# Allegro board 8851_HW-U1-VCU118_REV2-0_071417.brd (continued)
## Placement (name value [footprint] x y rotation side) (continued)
C1654  1UF  [0603]  124.75 155.32 270 bottom
C1655  1UF  [0603]  126.41 155.32 270 bottom
C1656  1UF  [0603]  133.51 155.32 270 bottom
C1657  1UF  [0603]  219.16 114.04 270 top
C1658  1UF  [0603]  219.16 117.22 90 top
C1659  1UF  [0603]  227.85 96.18 270 bottom
C1660  1UF  [0603]  238.04 116.49 90 bottom
C1661  1UF  [0603]  219.16 106.8 90 top
C1662  1UF  [0603]  219.16 103.63 270 top
C1663  1UF  [0603]  219.16 93.22 270 top
C1664  1UF  [0603]  219.16 96.39 90 top
C1665  1UF  [0603]  184.69 57.85 180 top
C1666  1UF  [0603]  187.87 57.85 0 top
C1667  1UF  [0603]  173.11 52.41 90 top
C1668  1UF  [0603]  182 43.27 90 bottom
C1669  1UF  [0603]  175.34 59.26 0 top
C1670  1UF  [0603]  175.34 56.47 0 top
C1671  1UF  [0603]  152.59 138.58 270 top
C1672  1UF  [0603]  152.59 141.76 90 top
C1673  1UF  [0603]  160.21 131.23 180 top
C1674  1UF  [0603]  169.1 141.14 180 bottom
C1675  1UF  [0603]  157.04 129.87 180 top
C1676  1UF  [0603]  157.09 132.98 180 top
C1677  1UF  [0402]  210.14 113.03 270 top
C1678  1UF  [0402]  210.14 102.61 270 top
C1679  1UF  [0402]  210.14 92.2 270 top
C1680  1UF  [0402]  184.08 66.76 180 top
C1681  1UF  [0402]  143.7 138.47 270 top
C1683  DNP  [0402]  234.36 103.29 270 bottom
C1684  DNP  [0402]  236.9 103.29 270 bottom
C1685  DNP  [0402]  239.44 103.29 270 bottom
C1688  DNP  [0402]  229.91 112.69 270 bottom
C1689  DNP  [0402]  228.99 110.2 270 bottom
C1690  DNP  [0402]  227.25 104.43 90 bottom
C1691  DNP  [0402]  227.5 100.49 270 bottom
C1694  DNP  [0402]  171.84 48.73 180 top
C1695  DNP  [0402]  171.84 45.57 0 top
C1698  DNP  [0402]  163.64 130.98 270 top
C1699  DNP  [0402]  166.8 130.98 90 top
C1700  0.22UF  [0402]  210.28 115.78 270 top
C1701  0.22UF  [0402]  210.28 105.36 270 top
C1702  0.22UF  [0402]  210.28 94.95 270 top
C1703  0.22UF  [0402]  186.24 66.76 180 top
C1704  0.22UF  [0402]  143.7 140.63 270 top
C1705  1000PF  [0402]  217.64 112.39 270 top
C1706  1000PF  [0402]  217.64 101.98 270 top
C1707  1000PF  [0402]  217.64 91.56 270 top
C1708  1000PF  [0402]  182.79 59.37 180 top
C1709  1000PF  [0402]  151.96 135.87 0 top
C1712  100PF  [0402]  239.01 115.87 180 top
C1713  100PF  [0402]  227.85 109.06 270 bottom
C1714  100PF  [0402]  239.44 105.57 270 bottom
C1715  100PF  [0402]  180.6 47.71 180 bottom
C1716  100PF  [0402]  180.33 50.1 90 bottom
C1717  100PF  [0402]  164.65 139.74 270 bottom
C1718  100PF  [0402]  162.26 139.47 180 bottom
C1719  6800PF  [0402]  229.03 108.11 90 bottom
C1720  22PF  [0402]  178.3 50.1 90 bottom
C1721  22PF  [0402]  162.26 137.44 180 bottom
C1722  8200PF  [0402]  171.84 48.73 0 bottom
C1723  8200PF  [0402]  163.64 130.98 90 bottom
C1724  100PF  [0402]  171.84 43.14 180 bottom
C1725  220PF  [0402]  169.22 130.98 270 bottom
C1731  10UF  [0603]  140.59 102.28 0 top
C1732  100UF  [1206]  138.93 130.5 270 top
C1733  100UF  [1206]  113.45 105.46 180 top
C1734  100UF  [1206]  99.57 31.42 0 bottom
C1735  100UF  [1206]  93.73 31.42 180 bottom
C1736  100UF  [1206]  93.73 31.42 180 top
C1737  100UF  [1206]  120.78 108.89 0 bottom
C1738  100UF  [1206]  121.03 126.8 0 bottom
C1739  100UF  [1206]  99.57 31.42 0 top
C1740  100UF  [1206]  121.03 126.8 0 top
C1741  100UF  [1206]  105.54 31.42 180 bottom
C1742  100UF  [1206]  168.66 117.02 90 bottom
C1743  100UF  [1206]  180.1 72.13 180 top
C1744  100UF  [1206]  180.1 69.38 180 top
C1745  100UF  [1206]  169.67 86.41 90 bottom
C1746  100UF  [1206]  126.13 105.46 90 bottom
C1747  100UF  [1206]  168.66 111.18 90 bottom
C1748  100UF  [1206]  126.13 105.46 90 top
C1749  100UF  [1206]  175.64 79.93 0 bottom
C1750  100UF  [1206]  129.41 28.5 0 top
C1751  100UF  [1206]  105.54 31.42 180 top
C1752  100UF  [1206]  129.41 28.5 0 bottom
C1753  1UF  [0603]  139.63 112.79 180 top
C1754  DNP  [0402]  136.4 112.19 90 top
C1755  4.7UF  [0402]  116.46 100.51 90 top
C1756  4.7UF  [0402]  84.07 55.93 180 top
C1757  100UF  [1206]  190.26 83.62 180 top
C1758  100UF  [1206]  190.26 91.49 180 top
C1759  0.1UF  [0402]  94.25 118.43 270 bottom
C1778  DNP  [0603]  208.55 115.75 270 top
C1779  DNP  [0603]  208.55 105.33 270 top
C1780  DNP  [0603]  208.55 94.92 270 top
C1781  0.1UF  [0402]  46.25 152.93 0 top
D4  BAT54T1G  [SOD_123]  196.09 169.71 270 bottom
D5  BAT54T1G  [SOD_123]  206.25 169.71 270 bottom
D7  BAT54T1G  [SOD_123]  27.69 89.2 270 top
D8  MMSZ4680T1G  [SOD_123]  47.87 101.8 180 bottom
D9  MMSZ4683T1G  [SOD_123]  139.99 20.61 90 top
D10  BAT54T1G  [SOD_123]  203.71 169.71 270 top
D11  BAT54T1G  [SOD_123]  198.63 169.71 270 top
D12  BAT54T1G  [SOD_123]  201.17 169.71 270 bottom
D13  BAT54T1G  [SOD_123]  201.17 169.71 270 top
D14  BAT54T1G  [SOD_123]  198.63 169.71 270 bottom
D15  BAS40-04  [SOT_23]  173.45 24.93 90 bottom
D16  MMSZ4683T1G  [SOD_123]  195.11 56.39 270 top
D17  BAT54T1G  [SOD_123]  196.09 169.71 270 top
D19  MMSZ4683T1G  [SOD_123]  197.55 150.57 90 top
D32  MMSZ4683T1G  [SOD_123]  146.03 129.79 0 bottom
D33  MMSZ4680T1G  [SOD_123]  233.3 56.57 0 top
D35  BAT54T1G  [SOD_123]  206.25 169.71 270 top
D36  MMSZ4680T1G  [SOD_123]  177.23 116.99 180 top
D37  MMSZ4680T1G  [SOD_123]  175.89 73.33 270 top
D38  MMSZ4680T1G  [SOD_123]  130.27 134.16 270 top
D39  MMSZ4683T1G  [SOD_123]  136.33 103.39 90 bottom
DS1  LED-YEL-SMT  [LED_0603]  42.8 147.5 180 top
DS2  LED-GRN-RED  [HSMF_C15X]  224.69 170.3 180 top
DS3  LED-GRN-RED  [HSMF_C15X]  211.33 166.41 180 top
DS4  LED-YELLOW-SMT  [LED_0603]  206.63 162.41 270 top
DS5  LED-YELLOW-SMT  [LED_0603]  208.66 162.73 90 top
DS6  LED-GRN-SMT  [LED_0603]  219.2 170.35 270 top
DS7  LED-GRN-SMT  [LED_0603]  220.85 170.35 270 top
DS8  LED-GRN-SMT  [LED_0603]  217.55 170.35 270 top
DS9  LED-GRN-SMT  [LED_0603]  215.9 170.35 270 top
DS10  LED-GRN-SMT  [LED_0603]  213.49 170.35 270 top
DS12  LED-GRN-SMT  [LED_0603]  211.71 170.35 270 top
DS13  LED-GRN-SMT  [LED_0603]  210.06 170.35 270 top
DS14  LED-YELLOW-SMT  [LED_0603]  225.68 162.26 270 top
DS15  LED-YELLOW-SMT  [LED_0603]  224.18 166.29 270 top
DS16  LED-YELLOW-SMT  [LED_0603]  222.38 166.29 270 top
DS17  LED-YELLOW-SMT  [LED_0603]  225.91 166.29 270 top
DS18  LED-GRN-SMT  [LED_0603]  208.41 170.35 270 top
DS19  LED-YELLOW-SMT  [LED_0603]  220.73 166.28 270 top
DS20  LED-GRN-SMT  [LED_0603]  214.61 153.13 0 top
DS21  LED-YELLOW-SMT  [LED_0603]  215.27 166.28 270 top
DS24  LED-YELLOW-SMT  [LED_0603]  219.08 166.28 270 top
DS25  LED-YELLOW-SMT  [LED_0603]  230.25 167.7 270 top
DS26  LED-GRN-SMT  [LED_0603]  204.61 143.56 0 top
DS27  LED-YELLOW-SMT  [LED_0603]  223.6 162.14 270 top
DS28  LED-YELLOW-SMT  [LED_0603]  221.49 162.26 270 top
DS34  LED-BLUE-SMT  [LED_0603]  228.45 170.77 90 top
DS36  LED-YELLOW-SMT  [LED_0603]  212.85 162.72 90 top
DS42  LED-GRN-RED  [HSMF_C15X]  5.28 132.36 270 top
DS43  LED-GRN-SMT  [LED_0603]  2.34 140.21 90 top
DS44  LED-GRN-SMT  [LED_0603]  2.51 133.43 90 top
DS45  LED-RED-SMT  [LED_0603]  5.15 139.7 0 top
DS46  LED-YELLOW-SMT  [LED_0603]  219.33 162.26 270 top
DS47  LED-YELLOW-SMT  [LED_0603]  210.69 162.72 90 top
DS48  LED-YELLOW-SMT  [LED_0603]  215.01 162.72 90 top
DS49  LED-YELLOW-SMT  [LED_0603]  217.12 166.25 270 top
EMICAGE1  EMI_CAGE  [EMI_CAGE_175X225]  173.49 124.51 0 top
J1  U95-T1Y1-100A  [CON_AMP_U95_T_1Y1_100A]  42.1 59.61 90 top
J2  -  [ASP_134486_01]  152.81 164.59 0 top
J3  87832-1420  [87832_1420]  17.61 81.25 270 top
J4  ZX62D_AB_5P8  [CON_HR_ZX62D_AB_5P8]  4.12 70.79 270 top
J5  -  [HDR_1X3]  198.25 20.62 270 top
J6  FIREFLY_RECEPT  [CON_SAMTEC_UEC5_UCC8]  48.37 69.13 180 top
J7  -  [HDR_2X4]  67.56 23.93 0 top
J8  -  [HDR_1X2]  200.91 26.34 270 top
J9  -  [HDR_1X2]  64.47 23.39 270 top
J10  RJ45  [7499111221A]  36.6 170.66 180 top
J11  RED  [TP_KEY_MINI]  50.22 132.38 270 top
J12  -  [HDR_1X2]  220.74 133.27 270 top
J13  RED  [TP_KEY_MINI]  18.8 125.02 0 top
J14  -  [HDR_1X2]  124.13 144.11 0 top
J15  39-30-1060  [CON_MOL_5569_6P]  230 145.73 0 top
J16  RED  [TP_KEY_MINI]  18.8 122.35 0 top
J17  RED  [TP_KEY_MINI]  50.16 129.59 270 top
J18  RED  [TP_KEY_MINI]  11.05 144.7 270 top
J19  RED  [TP_KEY_MINI]  10.92 148.89 270 top
J20  DNP  [TP_KEY_MINI]  179.2 15.49 0 top
J21  DNP  [TP_KEY_MINI]  192.53 57.58 90 top
J22  -  [ASP_184329_01]  82.8 164.59 0 top
J23  BLACK  [TP_KEY_MINI]  222 62.28 0 top
J24  BLACK  [TP_KEY_MINI]  172.97 144.45 0 top
J25  BLACK  [TP_KEY_MINI]  224.41 16.69 0 top
J26  BLACK  [TP_KEY_MINI]  199.52 129.34 180 top
J27  BLACK  [TP_KEY_MINI]  48.77 97.97 270 top
J28  DNP  [TP_KEY_MINI]  52.1 135.94 90 top
J30  32K10K-400L5  [32K10K_400_3VIA]  29.87 99.78 270 top
J31  32K10K-400L5  [32K10K_400_3VIA]  17.93 99.78 90 top
J32  32K10K-400L5  [32K10K_400_3VIA]  58.95 111.71 0 top
J33  32K10K-400L5  [32K10K_400_3VIA]  58.95 99.78 180 top
J34  32K10K-400L5  [32K10K_400_3VIA]  83.85 132.03 270 top
J35  32K10K-400L5  [32K10K_400_3VIA]  71.91 132.03 90 top
J36  22_11_2032  [HDR_1X3_LOCK_MOLEX]  28.7 66.34 270 top
J38  BLACK  [TP_KEY_MINI]  200.28 35.61 0 top
J39  -  [HDR_BOX_2X8]  235.51 27.2 90 top
J52  HDR_2X6_F_RA  [HDR_F2X6_PMOD]  231.19 68.8 90 top
J53  -  [HDR_2X6]  236.02 91.62 270 top
J54  DNP  [TP_KEY_MINI]  201.68 141.11 0 top
J58  DNP  [TP_KEY_MINI]  197.7 143.28 270 top
J63  DNP  [TP_KEY_MINI]  131.12 117.36 180 top
J65  DNP  [TP_KEY_MINI]  64.52 95.68 0 top
J70  DNP  [TP_KEY_MINI]  38.13 111.4 180 top
J73  22_11_2032  [HDR_1X3_LOCK_MOLEX]  171.98 32.34 90 top
J78  -  [HDR_1X4]  24.97 82.7 90 top
J82  SAMTEC-TSW-106-22-F-S-RA  [SAMTEC_TSW_106_22_S_RA]  11.07 102.05 180 top
J83  -  [CON_MOL_10P_5025700893]  20.5 170.2 180 bottom
J86  DNP  [TP_KEY_MINI]  10.35 124.78 180 top
J88  DNP  [TP_KEY_MINI]  163.04 143.08 0 top
J96  U95-T1Y1-100A  [CON_AMP_U95_T_1Y1_100A]  42.1 34.03 90 top
J97  DNP  [TP_KEY_MINI]  50.39 104.54 90 top
J99  DNP  [TP_KEY_MINI]  67.04 126.31 180 top
J100  DNP  [TP_KEY_MINI]  141.61 126.31 180 top
J101  DNP  [TP_KEY_MINI]  232.62 54 270 top
J103  DNP  [TP_KEY_MINI]  201.29 30.78 180 top
J104  DNP  [TP_KEY_MINI]  64.8 138.79 90 top
J105  -  [HDR_1X6]  90.37 129.14 0 top
J106  ZX62D_AB_5P8  [CON_HR_ZX62D_AB_5P8]  4.12 83.62 270 top
J107  DNP  [TP_KEY_MINI]  189.1 77.65 180 top
J108  DNP  [TP_KEY_MINI]  173.23 74.73 0 top
J109  DNP  [TP_KEY_MINI]  132.69 138.74 270 top
J110  -  [HDR_1X2]  26.94 130.72 270 top
L1  1.0UH  [1008]  64.77 53.51 0 top
L2  1.0UH  [1008]  64.63 57.49 180 top
L3  1UH  [IND_WURTH_7040]  192.18 143.18 90 top
L4  1.0UH  [IND_IHLP2525]  50.01 89.89 90 bottom
L5  1.0UH  [IND_IHLP2525]  42.39 89.89 90 bottom
L6  FERRITE-96  [IND_LAIRD_28F0121_1SR_10]  219.93 70.03 0 top
L7  1UH  [IND_WURTH_7040]  201.26 58.85 270 top
L8  10UH  [IND_74479887310]  206.44 66.04 270 bottom
L13  FERRITE-600  [0805]  124.84 27.36 270 bottom
L22  FERRITE-96  [IND_LAIRD_28F0121_1SR_10]  173.01 133.28 180 top
L31  FERRITE-220  [0603]  85.46 29.95 90 top
L34  FERRITE-220  [0603]  6.86 73.33 180 top
L35  FERRITE-220  [0603]  7.01 68.99 180 top
L48  10UH  [IND_74479887310]  186.49 135.99 90 bottom
L60  FERRITE-600  [0805]  29.42 133.55 180 top
L61  FERRITE-600  [0805]  26.42 135.1 270 top
L62  FERRITE-120  [0603]  20.75 143.13 90 bottom
L63  1.2UH  [IND_WURTH_2828]  14.03 123.64 90 top
L65  FERRITE-96  [IND_LAIRD_28F0121_1SR_10]  38.8 129.1 90 top
L66  680NH  [IND_WURTH_7040]  49.52 112.84 0 top
L67  10UH  [IND_74479887310]  43.67 116.96 0 bottom
L70  1.0UH  [1008]  64.61 34.79 0 top
L71  1.0UH  [1008]  64.64 26.59 0 top
L72  1.0UH  [1008]  64.63 30.65 180 top
L73  3.3UH  [IND_WURTH_4838]  61.87 125.94 90 top
L74  680NH  [IND_WURTH_7040]  224.26 53.39 90 top
L75  0.68UH  [IND_WURTH_1210]  194.54 47.62 0 top
L76  FERRITE-96  [IND_LAIRD_28F0121_1SR_10]  164.39 107.03 270 top
L77  FERRITE-96  [IND_LAIRD_28F0121_1SR_10]  208.31 42.47 180 top
L79  FERRITE-96  [IND_LAIRD_28F0121_1SR_10]  190.7 16.31 90 top
L80  1UH  [IND_WURTH_7040]  153.21 124.69 180 top
L82  10UH  [IND_74479887310]  160.4 120.52 180 bottom
L83  10UH  [IND_74479887310]  221.8 46.46 90 bottom
L85  10UH  [IND_74479887310]  193.76 24.86 90 bottom
L86  1.0UH  [1008]  64.61 62.65 0 top
L87  FERRITE-600  [0805]  122.81 27.36 270 bottom
L88  220NH  [IND_WURTH_7040]  187.22 71.78 180 top
L89  220NH  [IND_WURTH_7040]  138.74 138.35 270 top
L90  FERRITE-96  [IND_LAIRD_28F0121_1SR_10]  179.38 58.34 180 top
L91  FERRITE-96  [IND_LAIRD_28F0121_1SR_10]  149.28 133.01 270 top
L92  FERRITE-835  [BEAD_LAIRD_28C0236]  231.14 130.48 180 top
L93  FERRITE-220  [0603]  6.86 86.16 180 top
L94  FERRITE-220  [0603]  7.01 81.81 180 top
L95  50NH  [IND_COIL_CLB1108_4]  201.47 104.85 0 top
L96  3.3UH  [IND_VLS252012ET_3R3M]  232.21 96.18 90 bottom
L97  3.3UH  [IND_VLS252012ET_3R3M]  175.48 54.19 0 top
L98  3.3UH  [IND_VLS252012ET_3R3M]  158.65 135.16 0 top
MH1  MH_125_250  [MH_250H125]  236.22 170.61 0 top
MH2  MH_125_250  [MH_250H125]  118.62 137.59 0 top
MH3  MH_125_250  [MH_250H125]  131.32 21.39 0 top
MH4  MH_125_250  [MH_250H125]  5.46 146.11 0 top
MH5  MH_125_250  [MH_250H125]  236.22 16.59 0 top
MH6  MH_125_250  [MH_250H125]  7.49 9.32 0 top
MH7  MH_125_250  [MH_250H125]  7.49 94.72 0 top
NOREF  -  []  60.9 43.64 0 top
NOREF#2  -  [unnamed#2]  230.12 17.81 0 top
NOREF#3  -  []  55.61 164.59 0 top
NOREF#4  -  []  58.04 172.85 0 top
NOREF#5  -  []  63.4 42.64 90 top
NOREF#6  -  []  107.57 156.34 90 top
NOREF#7  -  []  82.8 164.59 0 top
NOREF#8  -  []  58.4 41.14 0 top
NOREF#9  -  []  107.57 156.34 90 top
NOREF#10  -  [unnamed#2]  12.32 12.85 0 top
NOREF#11  -  []  58.4 45.44 0 top
NOREF#12  -  []  51.32 166.6 0 top
NOREF#13  -  []  58.4 41.14 90 top
NOREF#14  -  []  107.57 156.34 90 top
NOREF#15  -  []  59.1 41.14 0 top
NOREF#16  -  []  58.4 41.84 0 top
NOREF#17  -  []  107.57 172.85 0 top
NOREF#18  -  []  109.99 161.54 90 top
NOREF#19  -  [unnamed#2]  231.14 172.75 0 top
NOREF#20  -  []  114.31 166.6 90 top
NOREF#21  -  []  109.99 161.54 0 top
NOREF#22  -  [unnamed#2]  12.19 12.85 180 bottom
NOREF#23  -  [unnamed#2]  231.01 172.75 180 bottom
NOREF#24  -  [unnamed#2]  230 17.81 180 bottom
Q1  FDS6681Z  [SOIC_8]  215.27 145.7 270 top
Q2  RUM001L02T2CL  [SOT_723]  219.91 159.48 180 bottom
Q3  RUM001L02T2CL  [SOT_723]  2.51 130.4 0 top
Q4  BSS138  [SOT_23]  223.52 158.15 90 top
Q5  RUM001L02T2CL  [SOT_723]  216.93 156.36 0 top
Q6  RUM001L02T2CL  [SOT_723]  219.33 156.37 0 top
Q7  RUM001L02T2CL  [SOT_723]  5.58 128.43 270 top
Q8  RUM001L02T2CL  [SOT_723]  201.87 156.81 180 bottom
Q9  FDPC8011S  [PWRCLIP_33]  191.42 136.7 180 top
Q10  RUM001L02T2CL  [SOT_723]  204.03 156.3 180 bottom
Q11  RUM001L02T2CL  [SOT_723]  208.1 159.48 180 bottom
Q12  RUM001L02T2CL  [SOT_723]  210 159.48 180 bottom
Q13  RUM001L02T2CL  [SOT_723]  212.03 159.48 180 bottom
Q14  RUM001L02T2CL  [SOT_723]  213.94 159.48 180 bottom
Q15  RUM001L02T2CL  [SOT_723]  215.84 159.48 180 bottom
Q16  RUM001L02T2CL  [SOT_723]  217.88 159.48 180 bottom
Q17  RUM001L02T2CL  [SOT_723]  208.1 156.3 0 top
Q18  RUM001L02T2CL  [SOT_723]  47.91 143.2 0 top
Q19  FDPC8011S  [PWRCLIP_33]  201.52 65.33 0 top
Q20  MMBT3904T  [SOT523]  202.56 57.2 180 bottom
Q21  RUM001L02T2CL  [SOT_723]  225.99 38.76 270 bottom
Q22  RUM001L02T2CL  [SOT_723]  177.04 28.12 180 bottom
Q23  RUM001L02T2CL  [SOT_723]  225.99 36.6 270 bottom
Q24  RUM001L02T2CL  [SOT_723]  204.85 160.45 0 top
Q25  MMBT3904T  [SOT523]  190.91 145.21 0 bottom
Q26  NDS331N  [SOT_23]  204.09 160.07 90 bottom
Q27  RUM001L02T2CL  [SOT_723]  88.66 100.69 0 top
Q28  RUM001L02T2CL  [SOT_723]  174.37 27.99 90 bottom
Q34  RUM001L02T2CL  [SOT_723]  2.34 137.23 0 top
Q35  RUM001L02T2CL  [SOT_723]  5 137.61 0 top
Q36  RUM001L02T2CL  [SOT_723]  214.67 156.32 0 top
Q37  RUM001L02T2CL  [SOT_723]  206.07 156.3 0 top
Q39  FDPC8011S  [PWRCLIP_33]  42.98 112.04 90 top
Q40  MMBT3904T  [SOT523]  51.71 113.21 270 bottom
Q41  RUM001L02T2CL  [SOT_723]  210.31 156.36 0 top
Q42  FDPC8011S  [PWRCLIP_33]  159.69 124.94 270 top
Q43  FDPC8011S  [PWRCLIP_33]  226.22 46.92 180 top
Q45  FDMS8558S  [PWR_56]  192.49 38.58 90 top
Q47  FDMS8558S  [PWR_56]  183.21 39.09 90 top
Q48  MMBT3904T  [SOT523]  151.26 124.51 90 bottom
Q49  MMBT3904T  [SOT523]  225.55 55.42 0 bottom
Q51  MMBT3904T  [SOT523]  194.9 48.1 0 bottom
Q52  RUM001L02T2CL  [SOT_723]  15.37 71.68 0 bottom
Q53  RUM001L02T2CL  [SOT_723]  13.46 71.68 0 bottom
Q54  RUM001L02T2CL  [SOT_723]  21.21 66.98 180 bottom
Q55  RUM001L02T2CL  [SOT_723]  17.27 71.68 0 bottom
Q56  RUM001L02T2CL  [SOT_723]  21.21 64.82 180 bottom
Q57  RUM001L02T2CL  [SOT_723]  19.18 64.19 180 bottom
Q58  NDS331N  [SOT_23]  204.39 164.87 90 bottom
Q59  RUM001L02T2CL  [SOT_723]  41.2 142.55 180 bottom
Q60  RUM001L02T2CL  [SOT_723]  44.58 145.75 90 top
Q61  SI2300DS  [SOT_23]  172.77 37.82 180 top
R1  4.70K  [0402]  58.88 47.24 180 bottom
R2  4.70K  [0402]  58.88 48.39 180 bottom
R3  DNP  [C402-25]  117.24 54.33 180 bottom
R4  240  [0402]  151.89 50.6 0 bottom
R5  240  [0402]  131.06 31.67 270 top
R6  4.70K  [0402]  131.06 15.07 90 bottom
R7  240  [0402]  157.72 38.85 180 bottom
R8  100  [0402]  77.95 132.03 180 top
R9  100  [0402]  176.77 15.74 270 bottom
R10  15  [0402]  58.06 16.2 90 bottom
R11  DNP  [0402]  55.63 16.18 90 bottom
R12  DNP  [0402]  56.9 16.18 270 bottom
R13  4.70K  [0402]  32.89 115.49 270 bottom
R14  10  [0402]  206.34 66.34 270 top
R15  100  [0402]  154.05 68.25 270 bottom
R16  10.0K  [0402]  27.69 87.85 270 bottom
R17  1.00K  [0402]  152.91 67.25 90 bottom
R18  1.00K  [0402]  152.91 69.25 270 bottom
R19  4.70K  [0402]  109.59 170.55 180 bottom
R20  1.00K  [0402]  151.89 67.25 270 bottom
R21  4.70K  [0402]  79.88 20.5 180 top
R22  1.00K  [0402]  151.89 69.25 90 bottom
R23  1.00K  [0402]  83.57 54.39 270 top
R24  1.00K  [0402]  83.57 52.39 90 top
R25  1.00K  [0402]  84.58 54.39 90 top
R26  2.21K  [0402]  30.1 139.34 0 top
R27  2.21K  [0402]  30.1 140.61 0 top
R28  4.70K  [0402]  201.6 20.88 0 top
R29  4.70K  [0402]  30.16 131.63 0 top
R30  4.70K  [0402]  30.1 135.53 0 top
R31  4.70K  [0402]  30.1 136.8 0 top
R32  24.9  [0402]  30.1 138.07 180 top
R33  261  [0402]  42.62 147.5 180 bottom
R34  2.21K  [0402]  43.68 141.15 180 top
R35  1.00K  [0402]  32.77 130.04 90 bottom
R36  100  [0402]  205.06 15.53 0 top
R37  100  [0402]  35.42 80.79 180 bottom
R38  100  [0402]  106.81 22.23 180 bottom
R39  10.0K  [0402]  43.68 140 180 top
R40  1.00K  [0402]  61.39 72.4 180 bottom
R41  1.00K  [0402]  61.39 71.25 180 bottom
R42  1.00K  [0402]  84.58 52.39 270 top
R43  432  [0402]  59.51 63.73 180 bottom
R44  10.0K  [0402]  31.75 146.58 90 top
R45  1.00K  [0402]  203.83 29.33 90 bottom
R46  1.00K  [0402]  220.19 27.02 0 bottom
R47  1.00K  [0402]  220.19 19.4 0 bottom
R48  1.00K  [0402]  227.4 29.33 90 bottom
R49  1.00K  [0402]  220.19 30.12 0 bottom
R50  1.00K  [0402]  61.39 69.98 180 bottom
R51  1.00K  [0402]  61.39 68.71 180 bottom
R52  1.00K  [0402]  106.68 131.5 180 bottom
R53  4.70K  [0402]  101.47 136.07 0 bottom
R54  DNP  [0402]  43.68 144.2 180 bottom
R55  DNP  [0402]  43.68 143.18 180 bottom
R56  DNP  [0402]  43.68 142.16 180 bottom
R57  DNP  [0402]  43.68 136.58 180 bottom
R58  4.99K  [0402]  50 141.09 270 top
R59  4.99K  [0402]  48.72 138.85 270 bottom
R60  DNP  [0402]  41.53 132.45 90 top
R61  DNP  [0402]  36.72 132.32 90 top
R62  DNP  [0402]  43.68 144.2 0 top
R63  DNP  [0402]  43.68 143.18 0 top
R64  DNP  [0402]  43.68 142.16 0 top
R65  DNP  [0402]  43.68 137.72 0 top
R66  DNP  [0402]  40.26 132.38 270 top
R67  DNP  [0402]  35.54 132.32 270 top
R68  DNP  [0402]  43.68 136.58 180 top
R69  1.00K  [0402]  43.68 135.43 0 bottom
R70  DNP  [0402]  42.92 133.59 90 top
R71  1.00K  [0402]  41.65 133.59 270 bottom
R72  4.99K  [0402]  47.72 142.87 0 bottom
R73  1.00K  [0402]  33.78 133.63 90 bottom
R74  9.53K  [0402]  216.63 65.71 0 bottom
R75  4.99K  [0402]  61.43 140.41 180 bottom
R76  1.00K  [0402]  81.86 105.04 90 top
R77  4.70K  [0402]  116.84 24.43 180 bottom
R78  10  [0201]  194.76 60.36 90 top
R79  10  [0201]  193.76 60.36 90 top
R80  1.43K  [0402]  202.56 59.23 180 bottom
R81  261  [0402]  27.12 150.83 270 top
R82  261  [0402]  46.25 151.31 180 top
R83  15  [0402]  8.31 134.88 0 bottom
R84  1.0M  [0402]  31.8 141.61 90 top
R85  200K  [0402]  49.23 73.99 90 bottom
R86  4.70K  [0402]  96.45 29.41 180 top
R87  0.005  [RES_WSLP_1206]  191.75 149.38 0 top
R88  100  [0402]  82.42 75.21 90 top
R89  200K  [0402]  59.13 50.8 180 bottom
R90  200K  [0402]  59.13 25.23 180 bottom
R91  4.99K  [0402]  47.71 146.94 0 bottom
R92  4.99K  [0402]  47.71 148.21 0 bottom
R93  4.99K  [0402]  61.43 142.44 180 bottom
R94  4.99K  [0402]  61.43 141.42 180 bottom
R95  10  [0402]  186.6 135.69 90 top
R96  4.70K  [0402]  4.88 135.93 0 top
R97  4.70K  [0402]  2.44 135.55 0 top
R98  0  [0402]  182.81 142.34 90 bottom
R99  10  [0201]  143.88 127.38 0 bottom
R100  10  [0201]  143.88 126.74 0 bottom
R101  10  [0201]  190.2 152.25 0 top
R102  10  [0201]  190.2 151.62 0 top
R103  10  [0201]  225.01 69.14 90 top
R104  10  [0201]  224.15 69.14 90 top
R105  10.0K  [0402]  88.65 100.25 0 bottom
R106  10.0K  [0402]  202.95 160.07 270 top
R107  4.70K  [0402]  175.39 36.75 90 top
R108  240  [0402]  152.27 63.93 90 bottom
R109  10  [0201]  193.51 119.2 0 bottom
R110  10  [0201]  193.51 118.06 0 bottom
R111  10  [0201]  173.2 71.53 90 top
R112  10  [0201]  172.44 71.53 90 top
R113  10  [0201]  136.31 129.91 0 top
R114  10  [0201]  136.31 130.67 0 top
R115  4.70K  [0402]  170.53 25.18 270 bottom
R116  4.70K  [0402]  151.89 38.91 0 bottom
R117  4.70K  [0201]  202 156.43 180 top
R118  4.70K  [0201]  204.16 155.92 180 top
R119  4.70K  [0201]  208.22 159.1 180 top
R120  4.70K  [0201]  210.13 159.1 180 top
R121  4.70K  [0201]  212.16 159.1 180 top
R122  4.70K  [0201]  214.07 159.1 180 top
R123  4.70K  [0201]  215.97 159.1 180 top
R124  4.70K  [0201]  218 159.1 180 top
R125  10.0K  [0402]  146.96 117.4 180 top
R126  4.70K  [0402]  33.03 86.92 0 bottom
R127  261  [0402]  208.66 162.73 90 bottom
R128  10.0K  [0402]  173.58 64.16 180 bottom
R129  10.0K  [0402]  173.08 66.45 180 bottom
R130  10.0K  [0402]  131.23 130.03 90 bottom
R131  200K  [0402]  225.55 71.05 180 top
R132  200K  [0402]  233.17 89.46 270 bottom
R133  15  [0402]  8.31 131.43 0 bottom
R134  2.00K  [0402]  214.61 153.13 0 bottom
R135  15  [0402]  8.18 132.57 0 bottom
R136  12.7K  [0402]  216.63 68.76 0 bottom
R137  26.1K  [0402]  216.63 66.72 0 bottom
R138  8.06K  [0402]  141 18.2 0 bottom
R139  2.2  [0603]  212.18 57.07 0 top
R140  DNP  [0402]  3.04 168.47 0 bottom
R141  DNP  [0402]  216.63 67.74 180 bottom
R142  200K  [0402]  25.4 115.87 180 bottom
R143  261  [0402]  208.41 169.96 90 bottom
R144  261  [0402]  210.06 169.96 90 bottom
R145  261  [0402]  211.71 169.96 90 bottom
R146  261  [0402]  213.49 169.96 90 bottom
R147  261  [0402]  215.9 169.96 90 bottom
R148  261  [0402]  217.55 169.96 90 bottom
R149  261  [0402]  219.2 169.96 90 bottom
R150  100  [0402]  153.76 60.63 90 bottom
R151  261  [0402]  220.85 169.96 90 bottom
R152  0.005  [RES_WSLP_1206]  51.12 107.23 180 top
R153  0.001  [1206]  203.15 35.15 90 top
R154  0  [0402]  210.25 59.43 270 bottom
R155  14.7K  [0402]  176.31 135.31 180 bottom
R156  1.00K  [0402]  205.07 56.82 90 bottom
R157  2.00K  [0402]  212.54 59.31 90 bottom
R158  2.00K  [0402]  211.4 59.43 270 bottom
R159  140K  [0402]  216.63 64.69 0 bottom
R160  10.2K  [0402]  141 17.06 180 bottom
R161  0.005  [RES_WSLP_1206]  203.73 52.65 180 top
R162  10.0K  [0402]  46.96 132.59 270 top
R163  10.0K  [0402]  46.41 140.36 180 top
R164  10.0K  [0402]  204.95 158.67 180 top
R165  2.00K  [0402]  205.23 162.66 90 top
R166  34.0K  [0402]  48.11 132.59 90 top
R167  10  [0402]  212.06 81.23 0 bottom
R168  0.0005  [RES_CSS2775]  190.34 103.58 180 top
R169  499  [0402]  235.89 100.74 180 top
R170  DNP  [0805]  207.78 84 180 bottom
R171  3.01K  [0402]  235.63 103.28 270 top
R172  0.005  [RES_WSLP_1206]  136.84 99.46 180 top
R173  0.005  [RES_WSLP_1206]  140.11 15.28 0 bottom
R174  100  [0402]  153.8 56.58 90 bottom
R175  100  [0402]  151.89 83.26 0 bottom
R176  100  [0402]  96.85 100.51 90 bottom
R177  1.00K  [0402]  83.57 76.21 270 top
R178  1.00K  [0402]  83.57 74.21 90 top
R179  1.00K  [0402]  84.58 76.21 90 top
R180  1.00K  [0402]  84.58 74.21 270 top
R181  1.00K  [0402]  152.62 57.58 270 bottom
R182  1.00K  [0402]  152.62 55.58 90 bottom
R183  1.00K  [0402]  151.35 57.58 90 bottom
R184  1.00K  [0402]  151.35 55.58 270 bottom
R185  1.00K  [0402]  152.62 61.63 270 bottom
R186  1.00K  [0402]  152.62 59.63 90 bottom
R187  1.00K  [0402]  151.35 61.63 90 bottom
R188  1.00K  [0402]  151.35 59.63 270 bottom
R189  4.99K  [0402]  137 121.99 180 bottom
R190  4.99K  [0402]  137 123.26 180 bottom
R191  4.70K  [0402]  157.85 26.19 180 bottom
R192  4.70K  [0402]  177.42 37.3 0 top
R193  DNP  [0402]  179.96 38.79 270 bottom
R194  100  [0402]  105.16 23.29 90 bottom
R195  100  [0402]  115.34 122.55 180 top
R196  4.7  [0402]  217.64 81.66 90 bottom
R197  100  [0402]  126.33 111.51 90 top
R198  11.0K  [0402]  47.73 141.58 180 bottom
R199  38.3K  [0402]  176.31 136.32 180 bottom
R200  2.49K  [0402]  46.36 140.39 180 bottom
R201  11.0K  [0402]  41.96 144.73 270 bottom
R202  2.49K  [0402]  41.96 144.73 90 top
R203  11.0K  [0402]  43.65 139.84 180 bottom
R204  2.49K  [0402]  43.61 141.07 0 bottom
R205  1.00K  [0402]  39.49 134.07 0 top
R206  1.00K  [0402]  37.36 134.04 180 top
R208  4.70K  [0402]  177.42 41.5 0 top
R210  10.0K  [0402]  177.04 26.47 180 bottom
R211  10.0K  [0402]  20.98 90.43 90 bottom
R212  10.0K  [0402]  19.94 90.43 90 bottom
R213  4.70K  [0402]  177.42 38.35 0 top
R214  12.7K  [0402]  176.31 133.28 180 bottom
R215  DNP  [0402]  143.26 24.43 270 bottom
R216  0  [0402]  77.34 124.13 0 bottom
R217  4.70K  [0402]  173.74 41.83 0 top
R218  4.70K  [0402]  179.96 40.94 270 bottom
R219  10.0K  [0402]  172.72 27.99 90 bottom
R220  DNP  [0402]  169.54 41.68 0 bottom
R221  DNP  [0402]  169.54 38.53 0 bottom
R222  DNP  [0402]  169.54 40.63 180 bottom
R223  DNP  [0402]  169.54 39.58 180 bottom
R229  DNP  [0402]  177.42 40.45 180 top
R231  2.2  [0603]  180.75 144.71 180 top
R236  4.70K  [0201]  220.04 159.1 0 top
R237  39.2  [0201]  75.51 101.61 270 top
R238  39.2  [0201]  79.07 101.61 270 top
R239  39.2  [0201]  78.05 105.04 270 top
R240  39.2  [0201]  80.84 101.61 270 top
R241  39.2  [0201]  79.32 105.04 270 top
R242  39.2  [0201]  85.67 101.61 270 top
R243  39.2  [0201]  76.78 105.04 270 top
R244  39.2  [0201]  84.4 105.04 270 top
R245  39.2  [0201]  83.13 105.04 270 top
R246  39.2  [0201]  72.21 101.61 270 top
R247  39.2  [0201]  69.16 101.61 270 top
R249  39.2  [0201]  66.87 101.61 270 top
R250  39.2  [0201]  69.16 105.04 270 top
R251  39.2  [0201]  66.11 101.61 270 top
R252  39.2  [0201]  76.53 101.61 270 top
R253  39.2  [0201]  75.51 105.04 270 top
R254  39.2  [0201]  74.49 101.61 270 top
R255  39.2  [0201]  83.64 101.61 270 top
R256  39.2  [0201]  84.65 101.61 270 top
R257  39.2  [0201]  71.95 105.04 270 top
R258  402  [0201]  72.97 105.04 270 top
R259  499  [0402]  70.43 105.04 90 top
R266  100  [0402]  78.24 22.47 270 top
R273  1.00K  [0402]  223.27 155.23 180 top
R299  100  [0402]  65.41 86.79 270 top
R300  100  [0402]  65.41 84.63 270 top
R308  10.0K  [0402]  109.59 167.75 180 bottom
R316  10.0K  [0402]  214.08 148.6 180 bottom
R318  DNP  [0402]  177.42 39.4 180 top
R319  DNP  [0402]  171.83 41.2 90 top
R321  10.0K  [0402]  193.8 169.65 0 bottom
R323  10.0K  [0402]  201.55 147.26 0 bottom
R324  10.0K  [0402]  228.06 38.76 270 bottom
R327  10.0K  [0402]  225.88 33.71 0 bottom
R331  10.0K  [0402]  126.67 141.44 0 bottom
R333  4.70K  [0402]  188.04 31.85 270 bottom
R334  10.0K  [0402]  216.99 156.05 180 bottom
R345  DNP  [0402]  51.17 172.2 180 bottom
R346  DNP  [0402]  111.76 169.85 90 bottom
R352  DNP  [0402]  147.95 114.35 180 top
R354  DNP  [0402]  49.87 138.85 90 bottom
R355  DNP  [0402]  51.15 141.09 90 top
R356  DNP  [0402]  61.43 139.39 0 bottom
R362  DNP  [0402]  176.31 134.29 0 bottom
R377  240  [0402]  154.18 76.89 270 bottom
R378  240  [0402]  151.89 74.35 0 bottom
R379  240  [0402]  84.07 67.11 180 top
R380  240  [0402]  151.89 49.45 0 bottom
R383  240  [0402]  151.89 75.49 0 bottom
R384  240  [0402]  154.05 74.6 90 bottom
R385  240  [0402]  76.34 57.06 180 top
R386  240  [0402]  76.34 42.96 180 top
R388  100K  [0402]  58.55 88.82 0 top
R389  100K  [0402]  58.55 87.68 0 top
R399  0  [0402]  147.95 115.62 0 top
R418  DNP  [0402]  116.79 31.7 270 top
R421  2.00K  [0402]  225.43 150.4 90 top
R422  4.70K  [0402]  175.39 38.91 90 top
R424  1.00K  [0402]  207.14 148.51 180 top
R434  1.00K  [0402]  187.87 145.21 270 bottom
R435  1.00K  [0402]  124.13 141.57 90 top
R460  2.00K  [0402]  204.58 144.96 0 top
R463  2.00K  [0402]  180.4 142.72 270 bottom
R464  2.00K  [0402]  181.67 142.47 90 bottom
R467  2.00K  [0402]  221.49 162.26 90 bottom
R468  2.00K  [0402]  223.6 162.26 90 bottom
R472  261  [0402]  226.19 170.05 270 bottom
R473  261  [0402]  223.27 171.07 180 bottom
R478  261  [0402]  225.68 162.26 270 bottom
R479  261  [0402]  188.85 169.21 90 bottom
R480  261  [0402]  188.85 167.33 270 bottom
R481  261  [0402]  222.38 165.77 270 bottom
R482  261  [0402]  224.16 165.9 270 bottom
R483  261  [0402]  225.93 165.9 270 bottom
R484  261  [0402]  230.25 167.32 270 bottom
R486  261  [0402]  220.73 165.9 270 bottom
R487  261  [0402]  219.08 165.9 270 bottom
R488  261  [0402]  215.27 166.28 270 bottom
R492  261  [0402]  212.85 162.72 90 bottom
R498  4.99K  [0402]  15.4 63.47 180 bottom
R499  4.99K  [0402]  221.23 151.8 180 top
R500  4.99K  [0402]  225.88 34.98 0 bottom
R501  4.99K  [0402]  225.88 31.17 0 bottom
R502  4.99K  [0402]  225.88 32.44 0 bottom
R515  140K  [0402]  176.31 137.34 180 bottom
R547  DNP  [0402]  133.86 31.67 90 bottom
R548  1.00K  [0402]  132.72 31.67 270 bottom
R553  200  [0402]  27.69 85.24 0 top
R554  200  [0402]  27.69 82.7 0 top
R556  100  [0201]  70.92 45.94 90 top
R557  100  [0201]  71.56 45.94 270 top
R558  100  [0201]  70.92 31.84 90 top
R559  100  [0201]  71.56 31.84 270 top
R560  1.00K  [0402]  131.57 31.67 270 bottom
R563  24.9  [0402]  164.1 15.22 0 top
R564  39.2  [0201]  71.19 101.61 270 top
R565  36  [0402]  83.27 95.03 0 top
R566  36  [0402]  83.26 93.76 0 top
R567  39.2  [0201]  66.87 105.04 270 top
R568  39.2  [0201]  85.67 105.04 270 top
R569  39.2  [0201]  65.86 105.04 270 top
R573  15  [0402]  9.32 156.36 0 bottom
R574  15  [0402]  9.32 158.26 0 bottom
R575  15  [0402]  5.26 171.09 0 bottom
R580  DNP  [0402]  140.79 115.64 0 bottom
R581  DNP  [0402]  137.01 115.64 0 bottom
R582  DNP  [0402]  140.78 114.36 180 top
R594  1.00K  [0402]  84.58 70.77 90 top
R595  1.00K  [0402]  84.58 68.77 270 top
R596  1.00K  [0402]  83.57 70.77 270 top
R597  1.00K  [0402]  83.57 68.77 90 top
R598  220  [0402]  228.45 170.82 90 bottom
R600  4.99K  [0402]  142.84 115.64 0 bottom
R601  4.99K  [0402]  137.01 114.36 0 top
R602  4.99K  [0402]  140.78 114.37 0 bottom
R603  4.99K  [0402]  50.89 142.87 0 top
R604  4.99K  [0402]  50.89 144.27 0 top
R607  4.99K  [0402]  47.72 144.52 0 bottom
R608  4.99K  [0402]  47.72 145.66 0 bottom
R611  4.99K  [0402]  61.41 149.08 180 bottom
R612  4.99K  [0402]  61.43 147.95 180 bottom
R613  4.99K  [0402]  61.43 146.82 180 bottom
R614  4.99K  [0402]  61.43 145.71 180 bottom
R617  4.99K  [0402]  61.43 144.58 180 bottom
R618  4.99K  [0402]  61.43 143.46 180 bottom
R621  4.99K  [0402]  140.54 116.78 0 bottom
R622  4.99K  [0402]  140.54 117.93 0 bottom
R623  4.99K  [0402]  140.54 119.07 0 bottom
R624  4.99K  [0402]  140.54 121.36 0 bottom
R625  4.99K  [0402]  140.54 120.21 0 bottom
R626  4.99K  [0402]  140.54 123.64 0 bottom
R627  4.99K  [0402]  140.54 122.5 0 bottom
R628  4.99K  [0402]  142.39 124.06 270 bottom
R629  4.99K  [0402]  137 124.53 180 bottom
R630  4.99K  [0402]  137 125.8 180 bottom
R637  1.50K  [0402]  226.19 153.07 270 top
R638  3.32K  [0402]  226.44 156.88 270 top
R639  10.0K  [0402]  224.92 153.07 270 bottom
R640  1.00K  [0402]  224.92 153.07 270 top
R682  4.99K  [0402]  58.44 138.77 90 bottom
R683  4.99K  [0402]  59.71 138.77 90 bottom
R687  100  [0402]  109.6 26.09 90 top
R692  100  [0402]  82.42 53.39 90 top
R700  240  [0402]  102.54 100.51 90 top
R704  240  [0402]  76.34 71.15 180 top
R705  240  [0402]  76.34 99.35 180 top
R706  100  [0201]  70.92 60.03 90 top
R707  100  [0201]  71.56 60.03 270 top
R708  100  [0201]  70.49 89.5 90 top
R709  100  [0201]  71.13 89.5 270 top
R712  1.43K  [0402]  190.37 143.05 0 bottom
R724  4.70K  [0402]  28.53 133.55 180 bottom
R726  4.70K  [0402]  5.84 128.8 180 bottom
R727  4.70K  [0402]  14.88 108.24 180 top
R728  4.70K  [0402]  14.88 109.51 180 top
R729  4.70K  [0402]  14.88 110.78 180 top
R730  4.70K  [0402]  14.88 112.05 180 top
R748  330  [0402]  2.61 128.56 180 top
R756  1.78K  [0402]  186.9 31.85 90 bottom
R772  20K  [0402]  24.31 132.13 0 bottom
R773  20K  [0402]  24.31 134.67 0 bottom
R774  20K  [0402]  24.31 133.4 0 bottom
R775  20K  [0402]  22.7 136.5 90 bottom
R776  20K  [0402]  24.31 135.94 180 bottom
R784  261  [0402]  5.94 134.26 90 bottom
R785  261  [0402]  5.64 140.59 90 bottom
R786  261  [0402]  5.21 141.15 0 top
R787  261  [0402]  5.87 131.59 270 bottom
R792  4.70K  [0402]  162.18 24.69 90 top
R793  4.70K  [0402]  163.39 24.68 90 top
R796  DNP  [C402-25]  112.24 72.33 180 bottom
R798  DNP  [C402-25]  123.75 70.84 90 bottom
R799  24.9  [0402]  160.7 19.27 270 top
R801  DNP  [0402]  162.18 15.59 270 top
R802  DNP  [0402]  168 15.22 90 top
R803  0  [0402]  160.96 15.59 90 top
R804  0  [0402]  168.01 17.4 90 top
R805  4.02K  [0402]  10.71 118.25 180 bottom
R808  5.9K  [0402]  27.43 112.57 180 bottom
R809  4.32K  [0402]  31.01 106.55 270 bottom
R810  15  [0402]  8.18 137.16 0 bottom
R811  15  [0402]  8.18 136.02 0 bottom
R812  15  [0402]  8.31 133.71 0 bottom
R813  3.65K  [0402]  10.73 119.39 180 bottom
R814  2.67K  [0402]  10.71 117.11 0 bottom
R815  3.32K  [0402]  27.41 108.82 180 bottom
R816  10.0K  [0402]  27.41 111.36 0 bottom
R817  10.0K  [0402]  30.1 114.99 0 bottom
R818  10.0K  [0402]  32.28 106.55 90 bottom
R819  10.0K  [0402]  27.41 107.55 0 bottom
R820  10.0K  [0402]  228.06 36.6 270 bottom
R821  10.0K  [0402]  35.28 106.35 180 bottom
R823  10.0K  [0402]  17 119.2 180 top
R824  10.0K  [0402]  42.29 105.64 270 bottom
R826  4.70K  [0402]  23.85 130.32 90 bottom
R827  20K  [0402]  31.75 115.49 90 bottom
R828  20K  [0402]  14.16 120.21 90 bottom
R830  2.00K  [0402]  219.33 162.34 90 bottom
R832  26.1K  [0402]  35.28 107.49 0 bottom
R837  68.1  [0402]  220.19 14.85 180 bottom
R838  68.1  [0402]  220.19 22.5 180 bottom
R839  68.1  [0402]  221.71 34.64 180 bottom
R840  68.1  [0402]  208.35 29.21 270 bottom
R841  68.1  [0402]  222.88 29.33 270 bottom
R854  4.70K  [0402]  13.29 114.25 90 top
R855  4.70K  [0402]  13.29 111.71 90 top
R856  4.70K  [0402]  13.29 109.17 90 top
R857  4.70K  [0402]  13.29 106.63 90 top
R858  4.70K  [0402]  10.04 71.56 90 bottom
R859  10.0K  [0402]  11.44 71.53 90 bottom
R860  DNP  [0402]  10.71 69.65 180 bottom
R861  10.0K  [0402]  55.02 149.61 270 bottom
R888  4.70K  [0402]  179.58 168.03 180 bottom
R890  10.0K  [0402]  179.58 165.24 180 bottom
R891  DNP  [0402]  120.69 170.46 180 bottom
R892  DNP  [0402]  181.29 169.53 180 bottom
R893  240  [0402]  76.34 85.25 180 top
R894  100  [0201]  70.92 74.13 90 top
R895  100  [0201]  71.56 74.13 270 top
R896  1.00K  [0402]  165 100.22 270 bottom
R897  36  [0402]  169.9 90.34 0 bottom
R898  36  [0402]  169.9 91.61 0 bottom
R899  499  [0402]  153.57 100.22 270 bottom
R900  100  [0402]  146.56 105.33 270 top
R901  100  [0402]  144.53 104.06 180 top
R902  39.2  [0201]  161.57 104.03 90 bottom
R903  39.2  [0201]  166.27 100.22 90 bottom
R904  39.2  [0201]  164.11 104.03 90 bottom
R905  39.2  [0201]  163.73 100.22 90 bottom
R906  39.2  [0201]  158.65 100.22 90 bottom
R907  39.2  [0201]  168.81 100.22 90 bottom
R908  39.2  [0201]  157.38 100.22 90 bottom
R909  39.2  [0201]  168.81 104.03 90 bottom
R910  39.2  [0201]  159.92 100.22 90 bottom
R911  39.2  [0201]  159.03 104.03 90 bottom
R912  39.2  [0201]  154.08 104.03 90 bottom
R913  39.2  [0201]  157.76 104.03 90 bottom
R914  39.2  [0201]  151.03 100.22 90 bottom
R915  39.2  [0201]  149.76 100.22 90 bottom
R916  39.2  [0201]  160.3 104.03 90 bottom
R917  39.2  [0201]  165.38 104.03 90 bottom
R918  39.2  [0201]  162.46 100.22 90 bottom
R919  39.2  [0201]  166.27 104.03 90 bottom
R920  39.2  [0201]  170.08 104.03 90 bottom
R921  39.2  [0201]  152.3 100.22 90 bottom
R922  402  [0201]  156.11 100.22 90 bottom
R923  39.2  [0201]  152.94 104.03 90 bottom
R924  39.2  [0201]  155.22 104.03 90 bottom
R925  39.2  [0201]  170.08 100.22 90 bottom
R926  39.2  [0201]  151.79 103.9 90 top
R928  100K  [0402]  145.16 98.98 0 bottom
R929  100K  [0402]  145.29 100.38 0 bottom
R930  240  [0402]  157.72 53.08 180 bottom
R931  240  [0402]  157.72 67.17 180 bottom
R932  240  [0402]  157.72 81.4 180 bottom
R933  240  [0402]  157.72 95.49 180 bottom
R934  4.70K  [0402]  109.6 159.62 180 bottom
R935  100  [0201]  165.09 43.04 90 bottom
R936  100  [0201]  164.45 43.04 270 bottom
R937  100  [0201]  165.09 57.14 90 bottom
R938  100  [0201]  164.45 57.14 270 bottom
R939  100  [0201]  165.09 71.24 90 bottom
R940  100  [0201]  164.45 71.24 270 bottom
R941  100  [0201]  165.09 85.33 90 bottom
R942  100  [0201]  164.45 85.33 270 bottom
R943  100  [0201]  165.09 28.82 90 bottom
R944  100  [0201]  164.45 28.82 270 bottom
R945  261  [0402]  210.69 162.72 90 bottom
R951  36  [0402]  94.5 116.38 90 bottom
R952  39.2  [0201]  102.24 121.52 180 top
R953  39.2  [0201]  95.4 125.96 270 top
R954  39.2  [0201]  92.23 108.36 90 top
R955  39.2  [0201]  84.25 120.17 0 top
R956  39.2  [0201]  102.24 116.57 180 top
R957  39.2  [0201]  102.24 120.76 180 top
R958  39.2  [0201]  84.25 112.17 0 top
R959  39.2  [0201]  84.25 114.17 0 top
R960  39.2  [0201]  84.25 111.17 0 top
R961  39.2  [0201]  102.24 114.66 180 bottom
R962  39.2  [0201]  102.24 116.57 180 bottom
R963  39.2  [0201]  84.25 115.17 0 top
R964  39.2  [0201]  84.25 119.17 0 top
R965  39.2  [0201]  89.23 108.36 90 top
R966  39.2  [0201]  84.25 117.17 0 top
R967  39.2  [0201]  94.49 125.91 270 top
R968  39.2  [0201]  102.24 115.55 180 top
R969  39.2  [0201]  102.24 120.76 180 bottom
R970  39.2  [0201]  84.25 113.17 0 top
R971  39.2  [0201]  84.25 118.17 0 top
R972  39.2  [0201]  102.24 117.33 180 top
R973  39.2  [0201]  102.24 117.33 180 bottom
R974  39.2  [0201]  102.24 114.66 180 top
R975  39.2  [0201]  91.23 108.36 90 top
R976  39.2  [0201]  96.11 108.34 90 top
R977  39.2  [0201]  90.23 108.36 90 top
R978  39.2  [0201]  102.24 115.55 180 bottom
R988  100  [0402]  93.73 124.13 0 bottom
R989  100  [0402]  100.36 108.01 270 bottom
R990  39.2  [0201]  86.23 118.54 270 bottom
R991  100  [0402]  56.24 135.9 270 bottom
R992  100  [0402]  54.63 135.36 180 bottom
R1001  240  [0402]  84.96 91.62 270 bottom
R1002  240  [0402]  84.96 78.54 90 bottom
R1007  249  [0402]  78.87 124.89 180 top
R1008  100K  [0402]  57.29 131.15 0 top
R1009  100K  [0402]  58.83 131.43 270 top
R1013  261  [0402]  215.01 162.72 90 bottom
R1015  2.40K  [0402]  143.36 19.07 270 top
R1016  4.70K  [0402]  142.88 26.21 0 top
R1017  DNP  [0402]  157.61 24.18 270 top
R1018  4.70K  [0402]  157.35 17.8 270 top
R1019  4.70K  [0402]  143.51 18.21 270 bottom
R1020  4.70K  [0402]  50.4 124.08 180 top
R1021  10  [0402]  43.36 116.86 0 top
R1022  0  [0402]  50.27 120.77 0 bottom
R1023  DNP  [C402-25]  125.24 57.33 0 bottom
R1024  DNP  [C402-25]  136.24 52.33 0 bottom
R1028  12.7K  [0402]  40.95 126.67 90 bottom
R1029  2.2  [0603]  52.63 122.7 90 top
R1052  1.78K  [0402]  50.4 124.08 0 bottom
R1070  DNP  [0402]  41.96 126.67 270 bottom
R1071  240  [0402]  84.07 58.34 180 top
R1072  240  [0402]  83.54 43.3 180 top
R1073  240  [0402]  84.07 59.49 180 top
R1074  1.00K  [0402]  50.85 115.59 180 bottom
R1075  2.00K  [0402]  50.4 123.06 180 bottom
R1076  2.00K  [0402]  50.27 121.92 0 bottom
R1077  140K  [0402]  45.01 126.77 90 bottom
R1078  26.1K  [0402]  44 126.67 90 bottom
R1079  953  [0402]  49.28 112.19 270 bottom
R1083  1.21K  [0402]  120.77 31.77 90 top
R1084  1.21K  [0402]  122.04 31.77 90 top
R1085  1.21K  [0402]  123.43 31.77 90 top
R1087  1.21K  [0402]  124.58 31.77 90 top
R1088  100  [0402]  136.02 31.55 90 bottom
R1090  4.02K  [0402]  57.46 118.3 270 bottom
R1092  4.70K  [0402]  62.84 63.86 270 bottom
R1094  4.70K  [0402]  58.88 21.67 180 bottom
R1095  4.70K  [0402]  58.88 22.81 180 bottom
R1096  12.7K  [0402]  59.13 118.67 180 top
R1097  3.65K  [0402]  57.61 120.95 90 top
R1100  20K  [0402]  60.48 120.86 270 bottom
R1101  4.70K  [0402]  21.69 156.49 180 bottom
R1103  DNP  [0402]  7.92 160.93 270 bottom
R1104  DNP  [0402]  9.32 160.93 270 bottom
R1105  39.2  [0201]  70.23 101.64 270 top
R1106  39.2  [0201]  149.3 103.85 90 top
R1107  953  [0402]  225.55 53.52 0 bottom
R1108  26.1K  [0402]  211.65 46.74 180 bottom
R1109  68.1K  [0402]  183.6 23.97 180 bottom
R1111  10  [0402]  160.71 119.99 180 top
R1112  0  [0402]  153.8 116.71 180 bottom
R1113  10  [0402]  221.9 46.15 90 top
R1114  0  [0402]  217.99 53.06 90 bottom
R1116  10  [0402]  195.79 20.54 90 top
R1124  4.70K  [0402]  22.91 139.09 90 bottom
R1125  38.3K  [0402]  160.07 110.34 270 bottom
R1126  21.5K  [0402]  211.62 45.77 180 bottom
R1127  1.43K  [0402]  153.54 124 90 bottom
R1130  12.7K  [0402]  183.6 22.7 180 bottom
R1131  12.7K  [0402]  163.12 110.34 270 bottom
R1132  12.7K  [0402]  161.09 110.32 270 bottom
R1133  12.7K  [0402]  211.62 43.74 180 bottom
R1135  6.19K  [0402]  192.53 51.49 0 bottom
R1136  2.2  [0603]  151.43 114.78 270 top
R1137  2.2  [0603]  215.55 55.42 180 top
R1139  2.2  [0603]  191.34 44.17 0 bottom
R1140  100  [0402]  175.94 20.05 0 top
R1141  100  [0402]  84.36 116.26 0 bottom
R1142  100  [0402]  67.21 113.85 0 bottom
R1143  DNP  [0402]  162.1 110.34 90 bottom
R1144  DNP  [0402]  211.62 44.76 0 bottom
R1145  249  [0402]  84.99 121.6 180 top
R1147  0  [0402]  191.85 31.85 90 bottom
R1148  0  [0402]  102.64 119.57 0 bottom
R1154  1.00K  [0402]  151.18 121.89 0 bottom
R1155  1.00K  [0402]  223.17 55.68 270 bottom
R1157  1.00K  [0402]  202.39 43.4 180 top
R1158  2.00K  [0402]  153.67 114.42 0 bottom
R1159  2.00K  [0402]  153.8 115.57 180 bottom
R1160  2.00K  [0402]  215.7 53.19 270 bottom
R1161  2.00K  [0402]  216.85 53.06 90 bottom
R1164  2.00K  [0402]  189.31 31.85 270 bottom
R1165  2.00K  [0402]  190.58 31.85 90 bottom
R1166  140K  [0402]  159.05 110.34 270 bottom
R1167  140K  [0402]  211.62 47.8 180 bottom
R1169  140K  [0402]  183.6 26.51 180 bottom
R1170  51.1K  [0402]  183.6 25.24 180 bottom
R1171  0.005  [RES_WSLP_1206]  146.32 127 90 top
R1172  0.005  [RES_WSLP_1206]  227.06 58.95 0 top
R1174  59.0K  [0402]  42.98 126.67 90 bottom
R1177  100  [0402]  82.42 69.77 90 top
R1183  261  [0402]  217.17 166.28 270 bottom
R1190  432  [0402]  58.45 36.17 0 bottom
R1192  10.0K  [0402]  62.56 120.75 180 bottom
R1193  10.0K  [0402]  98.1 126.22 90 bottom
R1194  10.0K  [0402]  95.56 126.35 90 bottom
R1195  10.0K  [0402]  100.64 126.22 90 bottom
R1196  20K  [0402]  21.51 134.11 180 bottom
R1197  20K  [0402]  24.94 143.87 0 top
R1198  100  [0402]  78.24 24.88 270 top
R1199  DNP  [0402]  183.27 43.01 90 bottom
R1200  DNP  [0402]  169.35 142.41 180 bottom
R1201  200  [0402]  232.71 116.24 90 bottom
R1203  0.001  [1206]  180.1 74.87 0 top
R1204  0.001  [1206]  133.03 134.54 270 top
R1205  115  [0402]  231.44 116.24 90 bottom
R1206  80.6  [0402]  233.98 116.24 90 bottom
R1207  80.6  [0402]  168.61 138.84 180 bottom
R1208  10  [0402]  212.06 112.47 0 bottom
R1209  10  [0402]  212.06 102.06 0 bottom
R1210  10  [0402]  212.06 91.65 0 bottom
R1211  10  [0402]  183.18 65.3 270 bottom
R1212  10  [0402]  145.35 136.34 270 bottom
R1213  576  [0402]  178.68 43.75 90 bottom
R1214  432  [0402]  168.61 136.81 180 bottom
R1215  1.8K  [0402]  226.58 109.06 270 bottom
R1216  29.4K  [0402]  239.01 113.33 0 top
R1217  29.4K  [0402]  182.99 47.38 270 bottom
R1218  29.4K  [0402]  165.69 142.39 270 bottom
R1219  2.15K  [0402]  239.01 114.6 180 top
R1220  2.15K  [0402]  180.6 46.67 180 bottom
R1221  2.15K  [0402]  165.69 139.74 270 bottom
R1222  499  [0402]  225.72 99.86 180 bottom
R1223  499  [0402]  233.73 100.75 180 bottom
R1224  499  [0402]  235.88 100.75 180 bottom
R1225  499  [0402]  238.04 100.75 180 bottom
R1226  499  [0402]  175.53 51.62 0 bottom
R1227  499  [0402]  162.26 136.04 0 bottom
R1228  100  [1206]  190.26 96.82 180 top
R1229  24.9K  [0402]  175.63 43.75 90 bottom
R1230  0  [0402]  235.25 116.23 270 bottom
R1231  0  [0402]  175.04 57.86 0 top
R1232  0  [0402]  157.34 131.45 180 top
R1233  2.49K  [0402]  171.82 49.98 180 bottom
R1234  2.49K  [0402]  162.39 130.96 270 bottom
R1235  DNP  [0402]  236.52 116.24 90 top
R1236  82.5  [0402]  171.84 43.57 180 top
R1237  220  [0402]  168.8 130.98 270 top
R1238  20.0K  [0402]  227.63 116.24 90 bottom
R1239  20.0K  [0402]  174.62 43.75 90 bottom
R1240  20.0K  [0402]  168.61 133.76 180 bottom
R1241  DNP  [0402]  227.85 111.22 270 bottom
R1244  DNP  [0402]  227.88 102.65 180 bottom
R1247  DNP  [0402]  181.62 65.64 90 bottom
R1248  DNP  [0402]  171.82 46.55 180 bottom
R1251  DNP  [0402]  143.7 136.31 90 bottom
R1252  DNP  [0402]  165.82 130.96 270 bottom
R1253  0  [0402]  228.77 100.49 90 bottom
R1254  0  [0402]  230.17 116.24 90 bottom
R1255  0  [0402]  171.82 49.98 180 top
R1256  0  [0402]  176.65 43.75 90 bottom
R1257  0  [0402]  162.39 130.96 270 top
R1258  0  [0402]  168.61 135.79 180 bottom
R1259  820  [0402]  171.82 45.4 0 bottom
R1260  680  [0402]  166.96 130.96 90 bottom
R1261  402  [0402]  226.58 111.22 270 bottom
R1262  332  [0402]  168.61 137.82 180 bottom
R1263  332  [0402]  171.84 44.57 180 top
R1264  332  [0402]  167.8 130.98 270 top
R1265  15K  [0402]  228.9 116.24 90 bottom
R1266  22.1K  [0402]  168.61 134.77 180 bottom
R1267  3.01K  [0402]  233.09 103.29 270 bottom
R1268  3.01K  [0402]  235.63 103.29 270 bottom
R1269  3.01K  [0402]  238.17 103.29 270 bottom
R1270  3.01K  [0402]  179.31 50.1 270 bottom
R1271  3.01K  [0402]  162.26 138.46 0 bottom
R1272  604  [0402]  228.52 104.43 270 bottom
R1273  604  [0402]  171.82 47.69 180 top
R1274  604  [0402]  164.67 130.96 270 top
R1275  4.7  [0402]  217.64 112.39 90 bottom
R1276  4.7  [0402]  217.64 101.98 90 bottom
R1277  4.7  [0402]  217.64 91.56 90 bottom
R1278  4.7  [0402]  182.79 59.37 0 bottom
R1279  4.7  [0402]  151.96 135.87 180 bottom
R1280  1.02K  [0402]  179.7 43.75 90 bottom
R1281  1.02K  [0402]  177.66 43.75 90 bottom
R1288  10.0K  [0402]  203.45 164.01 180 top
R1289  8.06K  [0402]  136.71 102.5 180 top
R1290  10.2K  [0402]  136.71 101.36 0 top
R1291  1.00K  [0402]  116.79 31.7 90 bottom
R1292  36  [0402]  93 116.43 0 bottom
R1293  2.40K  [0402]  157.99 18.59 270 bottom
R1317  DNP  [0805]  207.78 94.41 180 bottom
R1318  DNP  [0805]  207.78 104.83 180 bottom
R1319  DNP  [0805]  207.78 115.24 180 bottom
R1324  0  [0402]  6.83 87.76 0 top
R1325  0  [0402]  6.83 74.93 0 top
R1326  100  [0402]  83.54 42.14 180 top
R1327  4.70K  [0402]  179.32 33.83 270 bottom
R1328  DNP  [0402]  142.89 23.65 0 top
RP2  10.0K  [RP_EXB_0603X4]  200.52 150.29 0 bottom
RP3  10.0K  [RP_EXB_0603X4]  200.52 153.85 0 bottom
SW1  1101M2S3AQE2  [SW_102_1261_EV]  229.11 157.92 90 top
SW4  TL3301EF100QG  [SW_TL3301_G_4P]  96.01 134.16 0 top
SW5  TL3301EF100QG  [SW_TL3301_G_4P]  110.84 129.59 180 top
SW6  TL3301EF100QG  [SW_TL3301_G_4P]  206.09 24.76 270 top
SW7  TL3301EF100QG  [SW_TL3301_G_4P]  215.62 24.76 180 top
SW9  TL3301EF100QG  [SW_TL3301_G_4P]  225.14 24.76 90 top
SW10  TL3301EF100QG  [SW_TL3301_G_4P]  215.62 32.13 0 top
SW12  218-4LPSTRF  [SW_CTS_8P_SMT_HALF_PITCH]  60.4 70.36 90 top
SW14  TL3301EF100QG  [SW_TL3301_G_4P]  23.44 120.17 90 top
SW15  218-4LPSTRF  [SW_CTS_8P_SMT_HALF_PITCH]  21.29 110.14 270 top
SW16  218-4LPSTRF  [SW_CTS_8P_SMT_HALF_PITCH]  30.56 119.48 180 top
SW17  TL3301EF100QG  [SW_TL3301_G_4P]  215.62 17.39 180 top
U1  SOC_VU9P_FLGA2104_IRONWOOD  [SOC_2104_1MM_IRON]  118.24 65.84 90 top
U2  -  [PCIE_16LANE_EDGE]  45.65 3.49 0 top
U3  NVT2008PW  [TSSOP_20]  59.43 56.09 270 bottom
U4  MAX15301  [TQFN_32_EP]  216.47 47.98 0 bottom
U5  MAX8869EUE18+  [TSSOP_16_EP]  138.91 22.81 270 bottom
U6  MAX15301  [TQFN_32_EP]  211.78 64.51 180 bottom
U7  DP83867ISRGZ  [VQFN_48]  36.8 139.61 270 top
U8  INA226  [DGS_MSOP_10]  195.02 63.8 270 bottom
U9  MAX15301  [TQFN_32_EP]  158.88 115.19 90 bottom
U10  MAX15027  [TDFN_10_3X3_EP]  46.89 137.39 270 top
U11  VT1697SBFQX  [HPQFN_19_A]  213.96 85.93 180 top
U12  M24C08-WDW6TP  [TSSOP8_65P440X300MM]  145.91 112.88 180 bottom
U13  SN74AVC2T245  [QFN_RSW_10]  34.98 68.62 0 bottom
U14  250MHZ  [5MM_3_2MM_6P]  34.8 83.87 0 bottom
U15  MAX16052  [SOT23_6]  221.23 153.07 270 bottom
U16  50MOHM  [MURATA_BNX01]  210.84 134.56 180 top
U17  NVT2008PW  [TSSOP_20]  59.43 30.51 270 bottom
U18  10MHZ_TO_810MHZ  [SI570]  203.79 18.2 0 bottom
U19  SN74AVC8T245  [TSSOP_24]  58.26 144.16 0 top
U20  ICS85411AMLF  [SOIC_8]  59.09 42.03 180 bottom
U21  ICS85411AMLF  [SOIC_8]  35.42 76.29 90 bottom
U22  SN74AVC2T245  [QFN_RSW_10]  51.05 79.17 0 bottom
U23  INA226  [DGS_MSOP_10]  146.02 119.62 90 bottom
U24  TPS51200DRCT  [SON10_TPS51200]  62.4 88.03 180 top
U25  SN74LVC1G08  [SC70_5]  126.67 140.8 270 top
U26  NC7SZ66P5X  [SC70_5]  65.41 152.7 0 bottom
U27  INA226  [DGS_MSOP_10]  189.67 156.07 270 bottom
U28  TCA9548APWR  [TSSOP_24]  53.81 144.27 0 bottom
U29  INA226  [DGS_MSOP_10]  225.34 65.41 90 top
U30  MAX15301  [TQFN_32_EP]  181.16 137.52 0 bottom
U31  MAX6643  [MAX6643_QSOP16]  174.75 38.66 180 bottom
U32  10MHZ_TO_810MHZ  [SI570]  114.49 25 90 top
U33  SN74AVC2T245  [QFN_RSW_10]  54.48 79.17 0 bottom
U34  CP2105  [QFN_24]  16.16 67.79 0 top
U35  INA226  [DGS_MSOP_10]  188.42 119.41 0 bottom
U36  INA226  [DGS_MSOP_10]  173.32 66.57 90 top
U37  INA226  [DGS_MSOP_10]  131.36 129.53 0 top
U38  10MHZ_TO_810MHZ  [SI570]  95.95 24.85 180 top
U39  ICS854S006I  [TSSOP_24]  121.28 115.15 180 top
U40  ICS85411AMLF  [SOIC_8]  120.92 122.5 180 top
U41  NVT2008PW  [TSSOP_20]  219.84 73.33 0 bottom
U42  NVT2008PW  [TSSOP_20]  230.91 84.02 90 bottom
U43  MT25QU01  [SO16_50P300X413]  150.37 21.74 180 bottom
U44  NVT2008PW  [TSSOP_20]  44.25 76.76 0 bottom
U51  SN74AVC8T245  [TSSOP_24]  206.87 150.42 0 bottom
